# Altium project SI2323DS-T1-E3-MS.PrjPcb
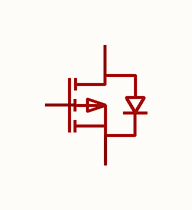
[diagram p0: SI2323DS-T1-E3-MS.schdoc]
1 sheet, 1 parts. Net scope: global (net labels, ports and power ports of the same name join across sheets).

## Sheet SI2323DS-T1-E3-MS.schdoc
size 127 x 101 mm

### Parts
Q?  si2323ds-t1-e3-ms  [SOT-23-3_L2.9-W1.3-P1.90-LS2.4-BR]  (value not drawn)

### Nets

Not connected (* = marked no-connect by the designer): Q? 1(G) 2(S) 3(D)

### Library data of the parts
Q? = si2323ds-t1-e3-ms: 数量:1个P沟道;漏源电压(Vdss):20V;连续漏极电流(Id):4.5A;导通电阻(RDS(on)):40mΩ@4.5V;耗散功率(Pd):1.56W;阈值电压(Vgs(th)):700mV;; Manufacturer: MSKSEMI(美森科); AddInBom: yes; ModelId: c62791f0466c4ae2a892c056b845b0ca; ModelName: SOT-23-3P_L2.9-W1.3-H1.0-LS2.4-P0.95; ModelTransform: 98.425,114.173,0,180,0,0,0.0005,-0.0005,0; Number: 1个P沟道; Drain to Source Voltage: 20V; Current - Continuous Drain(Id): 4.5A; Pd - Power Dissipation: 1.56W; Gate Threshold Voltage (Vgs(th)): 700mV; Gate Charge(Qg): 9.6nC@4.5V; Input Capacitance(Ciss): 850pF; Reverse Transfer Capacitance (Crss@Vds): 55pF; Type: P沟道; Output Capacitance(Coss): 70pF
